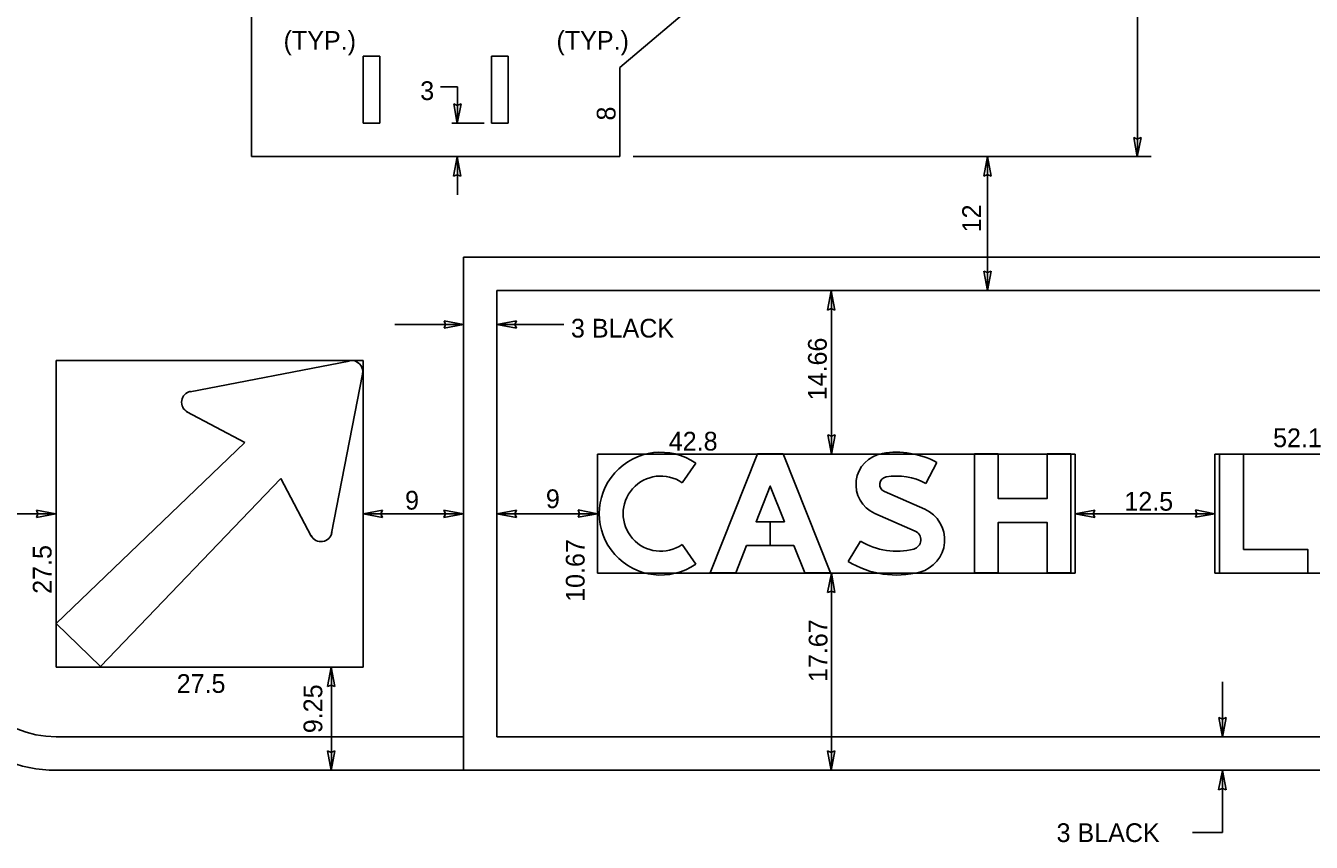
# Model space of a CAD drawing. Extents: x 319706 to 320019, y 1621790 to 1621996.
# Drawn here: x 319813.6 to 319909.6, y 1621816.2 to 1621877.2 of the extents above; entities that cross this region are included whole.
import ezdxf

# ---------------------------------------------------------------- set-up
doc = ezdxf.new("R2010")
doc.units = 0
for name, color, linetype in [('1', 7, 'Continuous'), ('40', 7, 'Continuous'), ('48', 7, 'Continuous'), ('52', 7, 'Continuous'), ('GSBWFill', 7, 'Continuous'), ('GSColorFill', 7, 'Continuous'), ('GSOutline', 7, 'Continuous'), ('SOILS_SP83_SHP', 7, 'Continuous')]:
    doc.layers.add(name, color=color, linetype=linetype)

msp = doc.modelspace()

# ---------------------------------------------------------------- linework, layer by layer
at = {"layer": '1'}
for p, q in [((319830.466, 1621867.375), (319830.466, 1621976.541)), ((319857.962, 1621874.041), (319892.962, 1621903.625)), ((319857.962, 1621867.375), (319857.962, 1621874.041)), ((319830.466, 1621867.375), (319857.962, 1621867.375)), ((319846.292, 1621859.875), (319985.882, 1621859.875)), ((319846.292, 1621821.541), (319846.292, 1621859.875)), ((319848.792, 1621857.375), (319983.382, 1621857.375)), ((319848.792, 1621824.041), (319848.792, 1621857.375)), ((319815.882, 1621829.249), (319815.882, 1621852.159)), ((319815.882, 1621852.159), (319838.792, 1621852.159)), ((319838.792, 1621829.249), (319838.792, 1621852.159)), ((319856.292, 1621836.266), (319856.292, 1621845.158)), ((319856.292, 1621845.158), (319891.959, 1621845.158)), ((319891.959, 1621836.266), (319891.959, 1621845.158)), ((319902.376, 1621845.158), (319945.792, 1621845.158)), ((319902.376, 1621836.266), (319902.376, 1621845.158)), ((319856.292, 1621836.266), (319891.959, 1621836.266)), ((319902.376, 1621836.266), (319945.792, 1621836.266)), ((319815.882, 1621829.249), (319838.792, 1621829.249)), ((319815.882, 1621824.041), (319846.292, 1621824.041)), ((319848.792, 1621824.041), (319975.882, 1621824.041)), ((319815.882, 1621821.541), (319975.882, 1621821.541))]:
    msp.add_line(p, q, dxfattribs=at)
for radius in [10, 7.5]:
    msp.add_arc((319815.882, 1621831.541), radius, 180, 270, dxfattribs=at)
at = {"layer": '40'}
for p, q in [((319840.049, 1621874.875), (319838.799, 1621874.875)), ((319838.799, 1621874.875), (319838.799, 1621869.875)), ((319840.049, 1621869.875), (319840.049, 1621874.875)), ((319849.629, 1621874.875), (319848.379, 1621874.875)), ((319848.379, 1621874.875), (319848.379, 1621869.875)), ((319849.629, 1621869.875), (319849.629, 1621874.875)), ((319838.799, 1621869.875), (319840.049, 1621869.875)), ((319848.379, 1621869.875), (319849.629, 1621869.875))]:
    msp.add_line(p, q, dxfattribs=at)
at = {"layer": '48'}
for p, q in [((319896.617, 1621911.958), (319896.617, 1621867.375)), ((319845.852, 1621872.594), (319844.58, 1621872.594)), ((319845.852, 1621872.594), (319845.852, 1621869.875)), ((319847.837, 1621869.875), (319845.434, 1621869.875)), ((319845.852, 1621867.375), (319845.852, 1621864.533)), ((319858.962, 1621867.375), (319897.617, 1621867.375)), ((319885.409, 1621867.375), (319885.409, 1621857.375)), ((319873.751, 1621845.158), (319873.751, 1621857.375)), ((319841.171, 1621854.849), (319846.292, 1621854.849)), ((319848.792, 1621854.849), (319853.78, 1621854.849)), ((319815.882, 1621840.708), (319805.882, 1621840.708)), ((319846.292, 1621840.708), (319838.792, 1621840.708)), ((319856.292, 1621840.708), (319848.792, 1621840.708)), ((319891.959, 1621840.708), (319902.376, 1621840.708)), ((319873.751, 1621836.266), (319873.751, 1621821.541)), ((319836.432, 1621821.541), (319836.432, 1621829.249)), ((319902.959, 1621824.041), (319902.959, 1621828.142)), ((319902.959, 1621816.884), (319902.959, 1621821.541)), ((319900.709, 1621816.884), (319902.959, 1621816.884))]:
    msp.add_line(p, q, dxfattribs=at)
at = {"layer": '52'}
for p, q in [((319845.832, 1621871.202), (319845.562, 1621871.312)), ((319845.562, 1621871.312), (319845.832, 1621869.862)), ((319845.832, 1621869.862), (319846.112, 1621871.312)), ((319846.112, 1621871.312), (319845.832, 1621871.202)), ((319896.592, 1621868.692), (319896.322, 1621868.802)), ((319896.322, 1621868.802), (319896.592, 1621867.352)), ((319896.592, 1621867.352), (319896.872, 1621868.802)), ((319896.872, 1621868.802), (319896.592, 1621868.692)), ((319845.832, 1621867.362), (319845.552, 1621865.912)), ((319846.102, 1621865.912), (319845.832, 1621867.362)), ((319885.409, 1621867.375), (319885.129, 1621865.925)), ((319885.679, 1621865.925), (319885.409, 1621867.375)), ((319845.552, 1621865.912), (319845.832, 1621866.022)), ((319845.832, 1621866.022), (319846.102, 1621865.912)), ((319885.129, 1621865.925), (319885.409, 1621866.035)), ((319885.409, 1621866.035), (319885.679, 1621865.925)), ((319885.409, 1621858.715), (319885.139, 1621858.825)), ((319885.139, 1621858.825), (319885.409, 1621857.375)), ((319885.409, 1621857.375), (319885.689, 1621858.825)), ((319885.689, 1621858.825), (319885.409, 1621858.715)), ((319873.732, 1621857.362), (319873.452, 1621855.912)), ((319874.002, 1621855.912), (319873.732, 1621857.362)), ((319873.452, 1621855.912), (319873.732, 1621856.022)), ((319873.732, 1621856.022), (319874.002, 1621855.912)), ((319846.292, 1621854.842), (319844.842, 1621855.122)), ((319844.842, 1621855.122), (319844.952, 1621854.842)), ((319844.952, 1621854.842), (319844.842, 1621854.572)), ((319844.842, 1621854.572), (319846.292, 1621854.842)), ((319850.242, 1621855.112), (319848.792, 1621854.842)), ((319848.792, 1621854.842), (319850.242, 1621854.562)), ((319850.132, 1621854.842), (319850.242, 1621855.112)), ((319850.242, 1621854.562), (319850.132, 1621854.842)), ((319873.751, 1621846.498), (319873.481, 1621846.608)), ((319873.481, 1621846.608), (319873.751, 1621845.158)), ((319873.751, 1621845.158), (319874.031, 1621846.608)), ((319874.031, 1621846.608), (319873.751, 1621846.498)), ((319815.862, 1621840.702), (319814.412, 1621840.982)), ((319814.412, 1621840.982), (319814.522, 1621840.702)), ((319814.522, 1621840.702), (319814.412, 1621840.432)), ((319814.412, 1621840.432), (319815.862, 1621840.702)), ((319840.242, 1621840.972), (319838.792, 1621840.702)), ((319838.792, 1621840.702), (319840.242, 1621840.422)), ((319840.132, 1621840.702), (319840.242, 1621840.972)), ((319840.242, 1621840.422), (319840.132, 1621840.702)), ((319846.282, 1621840.702), (319844.832, 1621840.982)), ((319844.832, 1621840.982), (319844.942, 1621840.702)), ((319844.942, 1621840.702), (319844.832, 1621840.432)), ((319844.832, 1621840.432), (319846.282, 1621840.702)), ((319850.242, 1621840.972), (319848.792, 1621840.702)), ((319848.792, 1621840.702), (319850.242, 1621840.422)), ((319850.132, 1621840.702), (319850.242, 1621840.972)), ((319850.242, 1621840.422), (319850.132, 1621840.702)), ((319856.292, 1621840.708), (319854.842, 1621840.988)), ((319854.842, 1621840.988), (319854.952, 1621840.708)), ((319854.952, 1621840.708), (319854.842, 1621840.438)), ((319854.842, 1621840.438), (319856.292, 1621840.708)), ((319893.409, 1621840.978), (319891.959, 1621840.708)), ((319891.959, 1621840.708), (319893.409, 1621840.428)), ((319893.299, 1621840.708), (319893.409, 1621840.978)), ((319893.409, 1621840.428), (319893.299, 1621840.708)), ((319902.376, 1621840.708), (319900.926, 1621840.988)), ((319900.926, 1621840.988), (319901.036, 1621840.708)), ((319901.036, 1621840.708), (319900.926, 1621840.438)), ((319900.926, 1621840.438), (319902.376, 1621840.708)), ((319873.751, 1621836.266), (319873.471, 1621834.816)), ((319874.021, 1621834.816), (319873.751, 1621836.266)), ((319873.471, 1621834.816), (319873.751, 1621834.926)), ((319873.751, 1621834.926), (319874.021, 1621834.816)), ((319836.422, 1621829.242), (319836.142, 1621827.792)), ((319836.692, 1621827.792), (319836.422, 1621829.242)), ((319836.142, 1621827.792), (319836.422, 1621827.902)), ((319836.422, 1621827.902), (319836.692, 1621827.792)), ((319902.942, 1621825.362), (319902.672, 1621825.472)), ((319902.672, 1621825.472), (319902.942, 1621824.022)), ((319902.942, 1621824.022), (319903.222, 1621825.472)), ((319903.222, 1621825.472), (319902.942, 1621825.362)), ((319836.412, 1621822.872), (319836.142, 1621822.982)), ((319836.142, 1621822.982), (319836.412, 1621821.532)), ((319836.412, 1621821.532), (319836.692, 1621822.982)), ((319836.692, 1621822.982), (319836.412, 1621822.872)), ((319873.732, 1621822.872), (319873.462, 1621822.982)), ((319873.462, 1621822.982), (319873.732, 1621821.532)), ((319873.732, 1621821.532), (319874.012, 1621822.982)), ((319874.012, 1621822.982), (319873.732, 1621822.872)), ((319902.942, 1621821.522), (319902.662, 1621820.072)), ((319903.212, 1621820.072), (319902.942, 1621821.522)), ((319902.662, 1621820.072), (319902.942, 1621820.182)), ((319902.942, 1621820.182), (319903.212, 1621820.072))]:
    msp.add_line(p, q, dxfattribs=at)
at = {"layer": 'GSBWFill'}
for p, q in [((319862.615, 1621843.016), (319863.63, 1621844.477)), ((319880.796, 1621842.97), (319881.636, 1621844.538)), ((319880.724, 1621841.036), (319877.714, 1621842.356)), ((319876.999, 1621840.727), (319880.01, 1621839.407)), ((319863.63, 1621836.944), (319862.615, 1621838.405)), ((319862.615, 1621838.405), (319862.615, 1621838.405)), ((319875.935, 1621838.653), (319875.011, 1621837.133))]:
    msp.add_line(p, q, dxfattribs=at)
for points in [[(319869.187, 1621840.104), (319869.187, 1621838.325), (319867.423, 1621838.325), (319866.611, 1621836.28), (319864.697, 1621836.28), (319868.231, 1621845.172), (319870.144, 1621845.172), (319873.678, 1621836.28), (319871.764, 1621836.28), (319870.951, 1621838.325), (319869.188, 1621838.325), (319869.188, 1621840.104), (319870.245, 1621840.104), (319869.187, 1621842.764), (319868.13, 1621840.104)], [(319891.639, 1621836.28), (319889.86, 1621836.28), (319889.86, 1621840.052), (319886.215, 1621840.052), (319886.215, 1621836.28), (319884.437, 1621836.28), (319884.437, 1621845.172), (319886.215, 1621845.172), (319886.215, 1621841.83), (319889.86, 1621841.83), (319889.86, 1621845.172), (319891.639, 1621845.172)], [(319904.509, 1621838.033), (319909.31, 1621838.033), (319909.31, 1621836.255), (319902.731, 1621836.255), (319902.731, 1621845.147), (319904.509, 1621845.147)]]:
    msp.add_lwpolyline(points, close=True, dxfattribs=at)
for radius in [4.586, 2.808]:
    msp.add_arc((319861.014, 1621840.711), radius, 55.21292, 304.78708, dxfattribs=at)
for centre, major_axis, start_param, end_param in [((319877.946, 1621842.885), (0, 2.356), 0.165591, 2.728374), ((319878.612, 1621838.895), (0, 6.402), 5.791375, 6.448776), ((319877.946, 1621842.885), (0, 0.578), 0.165591, 2.728374), ((319878.612, 1621838.895), (0, 4.624), 5.791375, 6.448776), ((319879.724, 1621838.756), (0, 2.49), 3.394273, 5.869966), ((319879.724, 1621838.756), (0, 0.711), 3.394273, 5.869966), ((319878.612, 1621843.06), (0, 5.157), 2.595642, 3.394273), ((319878.612, 1621843.06), (0, 6.936), 2.595642, 3.394273)]:
    msp.add_ellipse(centre, major_axis=major_axis, ratio=0.999996, start_param=start_param, end_param=end_param, dxfattribs=at)
at = {"layer": 'GSColorFill'}
for p, q in [((319862.615, 1621843.016), (319863.63, 1621844.477)), ((319880.796, 1621842.97), (319881.636, 1621844.538)), ((319880.724, 1621841.036), (319877.714, 1621842.356)), ((319876.999, 1621840.727), (319880.01, 1621839.407)), ((319863.63, 1621836.944), (319862.615, 1621838.405)), ((319862.615, 1621838.405), (319862.615, 1621838.405)), ((319875.935, 1621838.653), (319875.011, 1621837.133))]:
    msp.add_line(p, q, dxfattribs=at)
for points in [[(319869.187, 1621840.104), (319869.187, 1621838.325), (319867.423, 1621838.325), (319866.611, 1621836.28), (319864.697, 1621836.28), (319868.231, 1621845.172), (319870.144, 1621845.172), (319873.678, 1621836.28), (319871.764, 1621836.28), (319870.951, 1621838.325), (319869.188, 1621838.325), (319869.188, 1621840.104), (319870.245, 1621840.104), (319869.187, 1621842.764), (319868.13, 1621840.104)], [(319891.639, 1621836.28), (319889.86, 1621836.28), (319889.86, 1621840.052), (319886.215, 1621840.052), (319886.215, 1621836.28), (319884.437, 1621836.28), (319884.437, 1621845.172), (319886.215, 1621845.172), (319886.215, 1621841.83), (319889.86, 1621841.83), (319889.86, 1621845.172), (319891.639, 1621845.172)], [(319904.509, 1621838.033), (319909.31, 1621838.033), (319909.31, 1621836.255), (319902.731, 1621836.255), (319902.731, 1621845.147), (319904.509, 1621845.147)]]:
    msp.add_lwpolyline(points, close=True, dxfattribs=at)
for radius in [4.586, 2.808]:
    msp.add_arc((319861.014, 1621840.711), radius, 55.21292, 304.78708, dxfattribs=at)
for centre, major_axis, start_param, end_param in [((319877.946, 1621842.885), (0, 2.356), 0.165591, 2.728374), ((319878.612, 1621838.895), (0, 6.402), 5.791375, 6.448776), ((319877.946, 1621842.885), (0, 0.578), 0.165591, 2.728374), ((319878.612, 1621838.895), (0, 4.624), 5.791375, 6.448776), ((319879.724, 1621838.756), (0, 2.49), 3.394273, 5.869966), ((319879.724, 1621838.756), (0, 0.711), 3.394273, 5.869966), ((319878.612, 1621843.06), (0, 5.157), 2.595642, 3.394273), ((319878.612, 1621843.06), (0, 6.936), 2.595642, 3.394273)]:
    msp.add_ellipse(centre, major_axis=major_axis, ratio=0.999996, start_param=start_param, end_param=end_param, dxfattribs=at)
at = {"layer": 'GSOutline'}
for p, q in [((319862.615, 1621843.016), (319863.63, 1621844.477)), ((319880.796, 1621842.97), (319881.636, 1621844.538)), ((319880.724, 1621841.036), (319877.714, 1621842.356)), ((319876.999, 1621840.727), (319880.01, 1621839.407)), ((319863.63, 1621836.944), (319862.615, 1621838.405)), ((319862.615, 1621838.405), (319862.615, 1621838.405)), ((319875.935, 1621838.653), (319875.011, 1621837.133))]:
    msp.add_line(p, q, dxfattribs=at)
for points in [[(319870.951, 1621838.325), (319867.423, 1621838.325), (319866.611, 1621836.28), (319864.697, 1621836.28), (319868.231, 1621845.172), (319870.144, 1621845.172), (319873.678, 1621836.28), (319871.764, 1621836.28)], [(319891.639, 1621836.28), (319889.86, 1621836.28), (319889.86, 1621840.052), (319886.215, 1621840.052), (319886.215, 1621836.28), (319884.437, 1621836.28), (319884.437, 1621845.172), (319886.215, 1621845.172), (319886.215, 1621841.83), (319889.86, 1621841.83), (319889.86, 1621845.172), (319891.639, 1621845.172)], [(319904.509, 1621838.033), (319909.31, 1621838.033), (319909.31, 1621836.255), (319902.731, 1621836.255), (319902.731, 1621845.147), (319904.509, 1621845.147)], [(319868.13, 1621840.104), (319870.245, 1621840.104), (319869.187, 1621842.764)]]:
    msp.add_lwpolyline(points, close=True, dxfattribs=at)
for radius in [4.586, 2.808]:
    msp.add_arc((319861.014, 1621840.711), radius, 55.21292, 304.78708, dxfattribs=at)
for centre, major_axis, start_param, end_param in [((319877.946, 1621842.885), (0, 2.356), 0.165591, 2.728374), ((319878.612, 1621838.895), (0, 6.402), 5.791375, 6.448776), ((319877.946, 1621842.885), (0, 0.578), 0.165591, 2.728374), ((319878.612, 1621838.895), (0, 4.624), 5.791375, 6.448776), ((319879.724, 1621838.756), (0, 2.49), 3.394273, 5.869966), ((319879.724, 1621838.756), (0, 0.711), 3.394273, 5.869966), ((319878.612, 1621843.06), (0, 5.157), 2.595642, 3.394273), ((319878.612, 1621843.06), (0, 6.936), 2.595642, 3.394273)]:
    msp.add_ellipse(centre, major_axis=major_axis, ratio=0.999996, start_param=start_param, end_param=end_param, dxfattribs=at)
at = {"layer": 'SOILS_SP83_SHP'}
for p, q in [((319837.762, 1621852.102), (319825.882, 1621849.802)), ((319836.442, 1621839.252), (319838.742, 1621851.132)), ((319825.652, 1621848.302), (319829.982, 1621846.022)), ((319829.982, 1621846.022), (319815.882, 1621832.512)), ((319819.202, 1621829.292), (319832.652, 1621843.342)), ((319832.652, 1621843.342), (319834.932, 1621839.022)), ((319815.882, 1621832.512), (319819.202, 1621829.292))]:
    msp.add_line(p, q, dxfattribs=at)
for centre, start, end in [((319837.939, 1621851.315), 349.10463, 100.89296), ((319826.083, 1621849.032), 100.89296, 241.97563), ((319835.656, 1621839.458), 208.0246, 349.10463)]:
    msp.add_arc(centre, 0.833, start, end, dxfattribs=at)

# ---------------------------------------------------------------- texts
at = {"layer": '48'}
for s, p in [('(TYP.)', (319832.862, 1621875.352)), ('(TYP.)', (319853.232, 1621875.352)), ('3', (319843.062, 1621871.602)), ('3 BLACK', (319854.312, 1621853.862)), ('52.1', (319906.723, 1621845.674)), ('42.8', (319861.617, 1621845.422)), ('9', (319841.932, 1621841.012)), ('9', (319852.442, 1621841.122)), ('12.5', (319895.622, 1621840.932)), ('27.5', (319824.882, 1621827.322)), ('3 BLACK', (319890.562, 1621816.182))]:
    msp.add_text(s, height=1.4, dxfattribs=at).set_placement(p)
for s, p in [('8', (319857.642, 1621870.072)), ('12', (319884.922, 1621861.719)), ('14.66', (319873.409, 1621849.173)), ('10.67', (319855.334, 1621834.12)), ('27.5', (319815.544, 1621834.72)), ('17.67', (319873.462, 1621828.132)), ('9.25', (319835.752, 1621824.312))]:
    msp.add_text(s, height=1.4, rotation=90, dxfattribs=at).set_placement(p)

doc.saveas('drawing.dxf')
